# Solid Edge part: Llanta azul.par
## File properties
Author: there
Template: iso metric part.par
Last saved by: there
Revision: 2
Application: Solid Edge
Precisión: 0.990
Username: there
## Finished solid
Body 1: solid body, 39 faces, 78 edges, 40 vertices.
  Faces by surface: cylinder 27, plane 12
  Edges by curve: circle 54, line 24
Bounding box of the edges (mm): 10.901 x 60.000 x 60.000, from (-3.001, -30, -30) to (7.9, 30, 30).
Cylindrical faces by radius (mm): R1.3 x1, R2.375 x8, R2.75 x2, R2.8 x1, R4.5 x1, R6.5 x1, R13.5 x4, R18.25 x4, R25.25 x2, R27.25 x2, R30 x1
Planar faces by outward normal: +x 5, +y 1, -x 5, -y 1
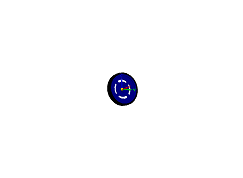
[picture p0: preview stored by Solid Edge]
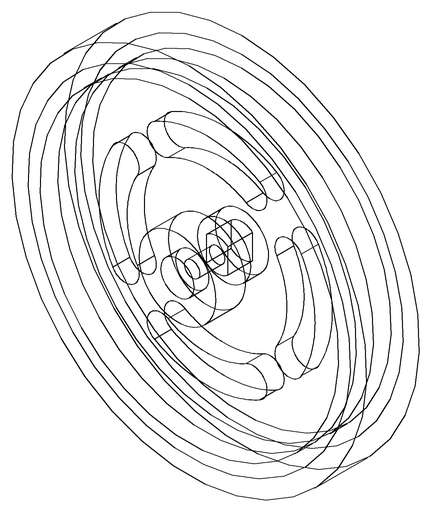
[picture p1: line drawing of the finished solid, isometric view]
